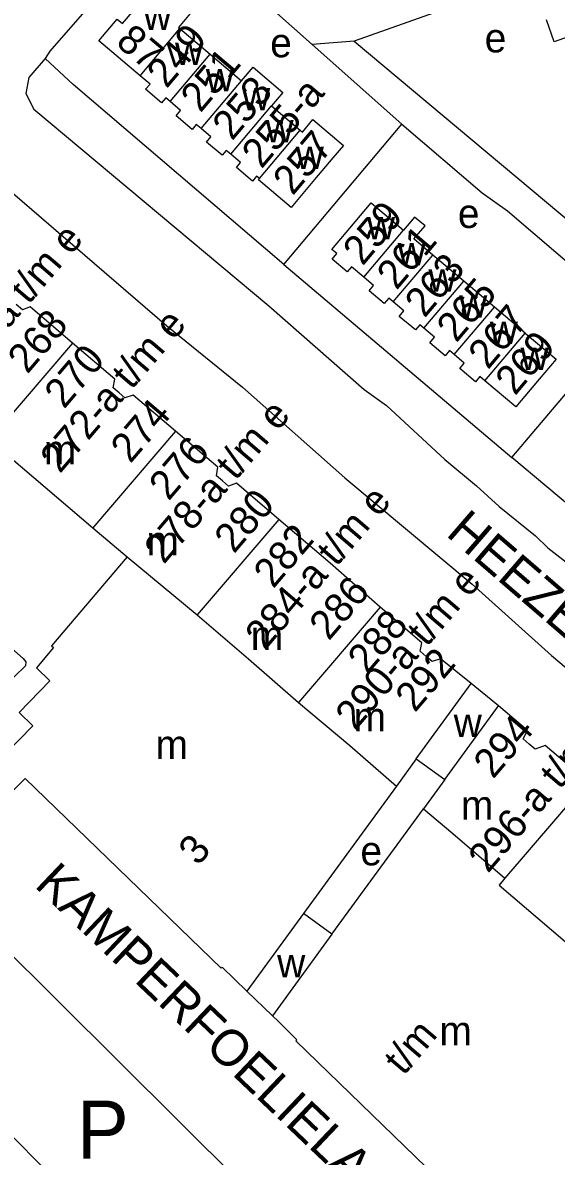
# Model space of a CAD drawing. Extents: x 161258 to 163262, y 380749 to 382054.
# Drawn here: x 162701.6 to 162775, y 381524.9 to 381680.9 of the extents above; entities that cross this region are included whole.
import ezdxf

# ---------------------------------------------------------------- set-up
doc = ezdxf.new("R2010")
doc.units = 0
for name, color, linetype in [('BLT_Basislijn', 7, 'Continuous'), ('BLT_Bebouwing', 7, 'Continuous'), ('BLT_Centroide', 7, 'Continuous'), ('BLT_Huisnummer', 7, 'Continuous'), ('BLT_Huisnummer_ tussenligend', 7, 'Continuous'), ('BLT_Huisnummer_reeks', 7, 'Continuous'), ('BLT_Onderdoorgang_en_onderverdeling', 7, 'Continuous'), ('BLT_Onderverdeling_panden', 7, 'Continuous'), ('BLT_Straatnaam', 7, 'Continuous'), ('BLT_Tekst_parkeren', 7, 'Continuous')]:
    doc.layers.add(name, color=color, linetype=linetype)

msp = doc.modelspace()

# ---------------------------------------------------------------- linework, layer by layer
at = {"layer": 'BLT_Basislijn'}
for p, q in [((162778.53, 381689.45), (162747.24, 381678.31)), ((162732.8, 381685.56), (162741.45, 381677.86)), ((162747.24, 381678.31), (162741.45, 381677.86)), ((162741.45, 381677.86), (162753.76, 381666.9)), ((162737.56, 381647.58), (162753.76, 381666.9)), ((162737.56, 381647.58), (162768.93, 381621.03)), ((162800.21, 381594.62), (162768.93, 381621.03)), ((162692.32, 381560.31), (162747.26, 381505.69)), ((162680.29, 381547.78), (162734.07, 381493.33))]:
    msp.add_line(p, q, dxfattribs=at)
for points in [[(162721.06, 381695.33), (162720.68, 381694.88), (162711.69, 381684.48), (162710.78, 381683.14), (162705.36, 381676.93), (162704.72, 381675.94)], [(162747.24, 381678.31), (162787.78, 381644.37), (162789.81, 381643.84), (162792.86, 381646.77)], [(162704.72, 381675.94), (162702.47, 381673.33), (162702.07, 381671.1), (162703.17, 381668.93), (162735.47, 381641.89), (162748.6, 381630.36), (162751.66, 381628.16), (162759.69, 381620.73), (162764.06, 381617.13), (162767.15, 381614.28), (162772.17, 381610.24), (162773.88, 381608.59), (162777.16, 381606.01)], [(162737.56, 381647.58), (162708.58, 381672.33), (162704.72, 381675.94)], [(162753.76, 381666.9), (162764.85, 381657.46), (162768.3, 381654.94), (162785.1, 381640.6)], [(162687.22, 381654.92), (162690.83, 381659.65), (162693.61, 381660.69), (162695.2, 381660.74), (162697.21, 381659.99), (162721.45, 381639.16), (162731.84, 381630.7), (162745.96, 381618.23), (162763.46, 381603.58), (162774.35, 381593.8), (162799.77, 381572.39), (162799.97, 381572.2)], [(162768.93, 381621.03), (162778.59, 381632.46), (162785.1, 381640.6)], [(162662.95, 381627.78), (162701.67, 381593.38), (162702.06, 381592.9), (162701.99, 381592.36), (162697.42, 381587.94)]]:
    msp.add_lwpolyline(points, dxfattribs=at)
at = {"layer": 'BLT_Bebouwing'}
for p, q in [((162723.24, 381680.05), (162727.41, 381676.52)), ((162727.41, 381676.52), (162731.74, 381672.86)), ((162735.85, 381669.39), (162739.81, 381666.04)), ((162762.29, 381645.3), (162758.05, 381648.88)), ((162766.52, 381641.71), (162762.29, 381645.3)), ((162770.76, 381638.13), (162766.52, 381641.71)), ((162697.07, 381623.44), (162711.29, 381611.35)), ((162711.29, 381611.35), (162715.98, 381607.35)), ((162767.08, 381586.83), (162763.33, 381589.93)), ((162755.77, 381579.57), (162759.7, 381576.7)), ((162744.14, 381555.44), (162740.26, 381558.29)), ((162732.47, 381547.59), (162735.97, 381544.22))]:
    msp.add_line(p, q, dxfattribs=at)
for points in [[(162717.76, 381673.55), (162712.09, 381678.34), (162714.62, 381681.33), (162715.34, 381680.72), (162718.3, 381684.22), (162718.61, 381683.97), (162720.45, 381686.15), (162724.9, 381682.39), (162723.06, 381680.2), (162723.24, 381680.05)], [(162782.57, 381678.11), (162781.65, 381680.68), (162774.75, 381678.23), (162773.67, 381681.26)], [(162721.89, 381670), (162721.3, 381670.5), (162720.72, 381669.83), (162718.53, 381671.68), (162719.14, 381672.39), (162717.76, 381673.55)], [(162731.74, 381672.86), (162733.31, 381674.71), (162737.42, 381671.24), (162735.85, 381669.39)], [(162726.18, 381666.28), (162725.5, 381666.85), (162724.93, 381666.17), (162722.72, 381668.03), (162723.34, 381668.77), (162721.89, 381670)], [(162739.81, 381666.04), (162740.1, 381665.79), (162741.55, 381667.51), (162745.76, 381663.95), (162744.31, 381662.24), (162741.78, 381659.25), (162738.55, 381655.43), (162734.06, 381659.23), (162734.19, 381659.39)], [(162730.24, 381662.75), (162729.63, 381663.27), (162729.07, 381662.6), (162726.91, 381664.42), (162727.52, 381665.14), (162726.18, 381666.28)], [(162734.19, 381659.39), (162733.79, 381659.72), (162733.22, 381659.05), (162731.02, 381660.91), (162731.6, 381661.6), (162730.24, 381662.75)], [(162748.55, 381645.85), (162746.87, 381647.26), (162746.28, 381646.56), (162744.19, 381648.33), (162744.83, 381649.08), (162744.16, 381649.65), (162747.38, 381653.46), (162749.57, 381656.05), (162754.01, 381652.3)], [(162758.05, 381648.88), (162755.44, 381651.09), (162756.97, 381652.9), (162755.54, 381654.11), (162754.01, 381652.3)], [(162752.59, 381642.43), (162751.99, 381642.94), (162751.36, 381642.2), (162749.27, 381643.96), (162749.9, 381644.7), (162748.55, 381645.85)], [(162708.47, 381636.77), (162702.66, 381641.73), (162701.57, 381641.35), (162700.74, 381642.06)], [(162756.81, 381638.82), (162756.26, 381639.29), (162755.65, 381638.57), (162753.43, 381640.44), (162754.06, 381641.19), (162752.59, 381642.43)], [(162761, 381635.18), (162760.34, 381635.74), (162759.74, 381635.03), (162757.64, 381636.8), (162758.29, 381637.57), (162756.81, 381638.82)], [(162770.76, 381638.13), (162775, 381634.55), (162772.68, 381631.8), (162769.45, 381627.98), (162765.21, 381631.57)], [(162714.87, 381629.91), (162714.06, 381630.61), (162714.28, 381631.8), (162708.47, 381636.77)], [(162765.21, 381631.57), (162764.52, 381632.15), (162763.93, 381631.44), (162761.75, 381633.28), (162762.37, 381634.02), (162761, 381635.18)], [(162722.66, 381624.64), (162716.84, 381629.62), (162715.69, 381629.21), (162714.87, 381629.91)], [(162729.1, 381617.8), (162728.27, 381618.52), (162728.48, 381619.67), (162722.66, 381624.64)], [(162736.85, 381612.5), (162731.04, 381617.47), (162729.94, 381617.08), (162729.1, 381617.8)], [(162743.92, 381606.46), (162736.85, 381612.5)], [(162715.98, 381607.35), (162705.59, 381595.12), (162705.87, 381594.88), (162703.5, 381592.1), (162705.36, 381590.31), (162701.13, 381585.93), (162703.02, 381584.11), (162699.22, 381580.18), (162698.87, 381580.52), (162696.8, 381578.38), (162698.3, 381576.93), (162698.2, 381576.83), (162699.67, 381575.37)], [(162750.78, 381600.43), (162743.92, 381606.46)], [(162757.12, 381593.64), (162756.29, 381594.36), (162756.51, 381595.54), (162750.78, 381600.43)], [(162763.33, 381589.93), (162759.08, 381593.33), (162757.96, 381592.93), (162757.12, 381593.64)], [(162771.31, 381581.6), (162770.49, 381582.3), (162771.07, 381583.46), (162767.08, 381586.83)], [(162779.34, 381576.42), (162773.51, 381581.38), (162772.12, 381580.9), (162771.31, 381581.6)], [(162755.77, 381579.57), (162753.05, 381575.82)], [(162699.67, 381575.37), (162700.09, 381574.95), (162701.98, 381576.84), (162728.91, 381550.75), (162729.04, 381550.89), (162732.47, 381547.59)], [(162759.7, 381576.7), (162756.75, 381572.67)], [(162753.05, 381575.82), (162740.26, 381558.29)], [(162744.14, 381555.44), (162756.75, 381572.67)], [(162735.97, 381544.22), (162736.77, 381543.45), (162739.32, 381540.91), (162739.2, 381540.76), (162766.1, 381514.64), (162764.91, 381513.41), (162764.59, 381513.72), (162762.51, 381511.58), (162764, 381510.13), (162763.92, 381510.04), (162802.34, 381472.73)]]:
    msp.add_lwpolyline(points, dxfattribs=at)
at = {"layer": 'BLT_Onderdoorgang_en_onderverdeling'}
for p, q in [((162759.7, 381576.7), (162767.08, 381586.83)), ((162740.26, 381558.29), (162732.47, 381547.59)), ((162744.14, 381555.44), (162735.97, 381544.22))]:
    msp.add_line(p, q, dxfattribs=at)
msp.add_lwpolyline([(162755.77, 381579.57), (162755.77, 381579.57), (162763.33, 381589.93)], dxfattribs=at)
at = {"layer": 'BLT_Onderverdeling_panden'}
for p, q in [((162717.76, 381673.55), (162723.24, 381680.05)), ((162721.89, 381670), (162727.41, 381676.52)), ((162726.18, 381666.28), (162731.74, 381672.86)), ((162730.24, 381662.75), (162735.85, 381669.39)), ((162734.19, 381659.39), (162739.81, 381666.04)), ((162748.55, 381645.85), (162754.01, 381652.3)), ((162752.59, 381642.43), (162758.05, 381648.88)), ((162756.81, 381638.82), (162762.29, 381645.3)), ((162761, 381635.18), (162766.52, 381641.71)), ((162765.21, 381631.57), (162770.76, 381638.13)), ((162708.47, 381636.77), (162697.07, 381623.44)), ((162722.66, 381624.64), (162711.29, 381611.35)), ((162736.85, 381612.5), (162725.61, 381599.36)), ((162715.98, 381607.35), (162725.61, 381599.36)), ((162750.78, 381600.43), (162739.55, 381587.3)), ((162725.61, 381599.36), (162732.68, 381593.31)), ((162732.68, 381593.31), (162739.55, 381587.3)), ((162739.55, 381587.3), (162746.64, 381581.39)), ((162746.64, 381581.39), (162753.05, 381575.82)), ((162779.34, 381576.42), (162767.97, 381563.13)), ((162756.75, 381572.67), (162760.79, 381569.3)), ((162760.79, 381569.3), (162767.97, 381563.13))]:
    msp.add_line(p, q, dxfattribs=at)
msp.add_lwpolyline([(162767.97, 381563.13), (162767.16, 381562.18), (162781.55, 381549.89)], dxfattribs=at)

# ---------------------------------------------------------------- texts
at = {"layer": 'BLT_Centroide'}
for s, p in [('w', (162718.23, 381679.84)), ('e', (162765.18, 381676.76)), ('w', (162722.58, 381675.03)), ('e', (162735.67, 381676.09)), ('w', (162726.81, 381671.42)), ('w', (162731.8, 381668.77)), ('w', (162735.03, 381664.39)), ('w', (162739.19, 381660.73)), ('e', (162761.49, 381652.6)), ('w', (162748.98, 381651.05)), ('w', (162753.2, 381647.45)), ('w', (162757.44, 381643.86)), ('w', (162761.67, 381640.27)), ('w', (162765.88, 381636.66)), ('w', (162770.11, 381633.05)), ('m', (162704.53, 381620.1)), ('m', (162718.65, 381607.57)), ('m', (162733, 381594.55)), ('m', (162747.15, 381583.33)), ('w', (162760.92, 381582.56)), ('m', (162719.9, 381579.52)), ('m', (162761.91, 381571.2)), ('e', (162748.08, 381564.9)), ('w', (162736.63, 381549.48)), ('m', (162758.95, 381540.15))]:
    msp.add_text(s, height=4, dxfattribs=at).set_placement(p)
at = {"layer": 'BLT_Huisnummer'}
for s, rotation, p in [('87', 319.7859, (162714.26, 381677.91)), ('249', 49.7859, (162721.41, 381671.68)), ('253', 49.7878, (162730.43, 381664.5)), ('257', 49.7852, (162738.77, 381656.95)), ('259', 49.7887, (162748.39, 381647.28)), ('263', 49.7843, (162756.91, 381640.11)), ('269', 49.7939, (162769.35, 381629.42))]:
    msp.add_text(s, height=4, rotation=rotation, dxfattribs=at).set_placement(p)
at = {"layer": 'BLT_Huisnummer_ tussenligend'}
for s, rotation, p in [('251', 49.7859, (162726.07, 381668.34)), ('261', 49.7887, (162753.05, 381643.94)), ('265', 49.7843, (162761.28, 381636.7)), ('267', 49.7843, (162765.63, 381633))]:
    msp.add_text(s, height=4, rotation=rotation, dxfattribs=at).set_placement(p)
at = {"layer": 'BLT_Huisnummer_reeks'}
for s, height, rotation, p in [('255-a', 4, 49.7878, (162734.48, 381660.63)), ('266-a t/m e', 3.9999, 49.4633, (162692.56, 381630.43)), ('268', 4, 49.4631, (162702.26, 381632.4)), ('272-a t/m e', 3.9999, 49.4633, (162706.73, 381618.71)), ('270', 4, 49.4631, (162707.31, 381627.59)), ('274', 4, 49.4658, (162716.43, 381620.09)), ('278-a t/m e', 3.9999, 49.4633, (162721.04, 381606.22)), ('276', 4, 49.4658, (162721.7, 381614.94)), ('280', 4, 49.4691, (162730.69, 381607.68)), ('284-a t/m e', 3.9999, 49.4633, (162734.92, 381594.37)), ('282', 4, 49.4681, (162736.09, 381602.87)), ('286', 4, 49.4681, (162743.74, 381595.7)), ('290-a t/m e', 3.9999, 49.4633, (162747.34, 381583.32)), ('288', 4, 49.4503, (162749.03, 381591.08)), ('292', 4, 49.4588, (162755.58, 381585.82)), ('296-a t/m e', 3.9999, 49.4633, (162765.63, 381563.71)), ('294', 4, 49.4598, (162766.34, 381576.68)), ('3', 4, 49.4598, (162725.76, 381564.71)), ('t/m', 4, 49.4598, (162754.02, 381535.86))]:
    msp.add_text(s, height=height, rotation=rotation, dxfattribs=at).set_placement(p)
at = {"layer": 'BLT_Straatnaam'}
for s, rotation, p in [('HEEZERWEG', 319.2157, (162759.7, 381610.37)), ('KAMPERFOELIELAAN', 316.4279, (162703.1, 381562.05))]:
    msp.add_text(s, height=5, rotation=rotation, dxfattribs=at).set_placement(p)
at = {"layer": 'BLT_Tekst_parkeren'}
msp.add_text('P', height=8, dxfattribs=at).set_placement((162709.07, 381524.53))

doc.saveas('drawing.dxf')
